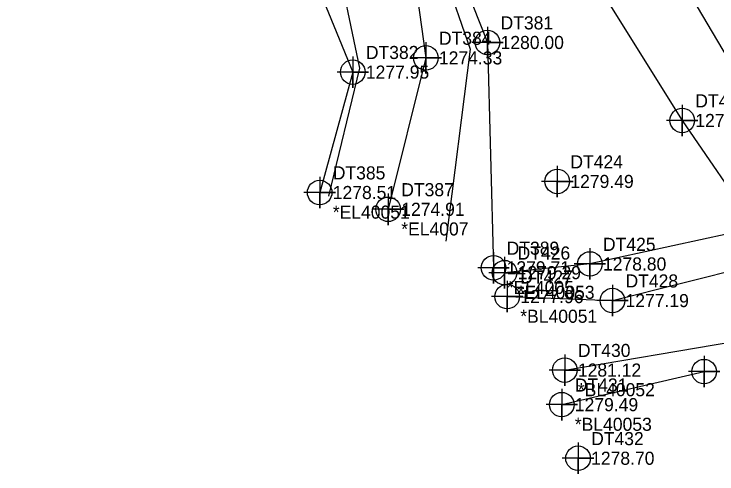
# Model space of a CAD drawing. Extents: x 1394009 to 1394411, y 957864 to 958364.
# Drawn here: x 1394149.6 to 1394283.7, y 957864.1 to 957951.9 of the extents above; entities that cross this region are included whole.
import ezdxf

# ---------------------------------------------------------------- set-up
doc = ezdxf.new("R2010")
doc.units = 0
for name, color, linetype in [('Exist DTM Breakline', 7, 'Continuous'), ('Exist DTM Breakline Cogo Comment', 7, 'Continuous'), ('Exist DTM Breakline Cogo Elevation', 7, 'Continuous'), ('Exist DTM Breakline Cogo Number', 7, 'Continuous'), ('Exist DTM Breakline Cogo Point CELL', 7, 'Continuous'), ('Exist DTM Breakline Underwater', 7, 'Continuous'), ('Exist DTM Breakline Underwater Cogo Comment', 7, 'Continuous'), ('Exist DTM Breakline Underwater Cogo Elevation', 7, 'Continuous'), ('Exist DTM Breakline Underwater Cogo Number', 7, 'Continuous'), ('Exist DTM Breakline Underwater Cogo Point CELL', 7, 'Continuous'), ('Exist DTM Crownline', 7, 'Continuous'), ('Exist DTM Regular Point Cogo Elevation', 7, 'Continuous'), ('Exist Hydro Stream or Body of Water', 7, 'Continuous'), ('Exist Roads EOP', 7, 'Continuous'), ('PH Exist DTM NCFMP LIDAR Elevation Point', 7, 'Continuous'), ('Raster_Level_0', 7, 'Continuous')]:
    doc.layers.add(name, color=color, linetype=linetype)

msp = doc.modelspace()

# ---------------------------------------------------------------- linework, layer by layer
at = {"layer": 'Exist DTM Breakline'}
for p, q in [((1394254.6438, 957883.9212), (1394290.1223, 957889.9518)), ((1394254.0597, 957877.3161), (1394281.2269, 957883.6237))]:
    msp.add_line(p, q, dxfattribs=at)
for points in [[(1394234.7161, 958087.1493), (1394208.4745, 958071.86), (1394207.051, 958069.7897), (1394210.8783, 958071.9618), (1394213.0858, 958066.3393), (1394211.818, 958067.823), (1394208.5647, 958061.9703), (1394223.9737, 958040.8216), (1394237.157, 958012.3346), (1394253.5006, 957985.8224), (1394267.2603, 957974.749), (1394288.6525, 957938.4432), (1394308.2436, 957898.2998)], [(1394205.7466, 958068.8917), (1394190.5711, 958057.2067), (1394189.0222, 958053.5957), (1394184.8806, 958043.8407), (1394186.4655, 958021.4355), (1394191.8774, 958003.2638), (1394213.2872, 957998.1706), (1394228.4733, 957975.4923), (1394239.8888, 957946.4968), (1394241.0497, 957903.4511)], [(1394149.71, 958037.8453), (1394149.558, 958011.2722), (1394170.1298, 957980.5225), (1394177.7403, 957975.0583), (1394196.6522, 957979.7455), (1394205.9408, 957961.0676), (1394214.1868, 957940.8417), (1394207.8738, 957917.8382)], [(1394202.6193, 958029.3354), (1394215.0019, 958016.2345), (1394221.6713, 958003.4334), (1394237.1401, 957997.6779), (1394243.3584, 957984.1351), (1394256.2425, 957964.9576), (1394277.0443, 957931.6004), (1394291.0752, 957911.067), (1394259.429, 957904.1903), (1394243.1444, 957902.5266)], [(1394243.646, 957897.9549), (1394263.7341, 957897.1943), (1394290.0967, 957903.851), (1394301.0447, 957893.1375)]]:
    msp.add_lwpolyline(points, dxfattribs=at)
at = {"layer": 'Exist DTM Breakline Cogo Point CELL'}
for points in [[(1394239.8888, 957949.4968), (1394239.8888, 957943.4968), (1394239.8888, 957946.4968), (1394242.8888, 957946.4968), (1394236.8888, 957946.4968)], [(1394214.1868, 957943.8417), (1394214.1868, 957937.8417), (1394214.1868, 957940.8417), (1394217.1868, 957940.8417), (1394211.1868, 957940.8417)], [(1394277.0443, 957934.6004), (1394277.0443, 957928.6004), (1394277.0443, 957931.6004), (1394280.0443, 957931.6004), (1394274.0443, 957931.6004)], [(1394207.8738, 957920.8382), (1394207.8738, 957914.8382), (1394207.8738, 957917.8382), (1394210.8738, 957917.8382), (1394204.8738, 957917.8382)], [(1394241.0497, 957906.4511), (1394241.0497, 957900.4511), (1394241.0497, 957903.4511), (1394244.0497, 957903.4511), (1394238.0497, 957903.4511)], [(1394259.429, 957907.1903), (1394259.429, 957901.1903), (1394259.429, 957904.1903), (1394262.429, 957904.1903), (1394256.429, 957904.1903)], [(1394243.1444, 957905.5266), (1394243.1444, 957899.5266), (1394243.1444, 957902.5266), (1394246.1444, 957902.5266), (1394240.1444, 957902.5266)], [(1394243.646, 957900.9549), (1394243.646, 957894.9549), (1394243.646, 957897.9549), (1394246.646, 957897.9549), (1394240.646, 957897.9549)], [(1394263.7341, 957900.1943), (1394263.7341, 957894.1943), (1394263.7341, 957897.1943), (1394266.7341, 957897.1943), (1394260.7341, 957897.1943)], [(1394254.6438, 957886.9212), (1394254.6438, 957880.9212), (1394254.6438, 957883.9212), (1394257.6438, 957883.9212), (1394251.6438, 957883.9212)], [(1394281.2269, 957886.6237), (1394281.2269, 957880.6237), (1394281.2269, 957883.6237), (1394284.2269, 957883.6237), (1394278.2269, 957883.6237)], [(1394254.0597, 957880.3161), (1394254.0597, 957874.3161), (1394254.0597, 957877.3161), (1394257.0597, 957877.3161), (1394251.0597, 957877.3161)]]:
    msp.add_lwpolyline(points, dxfattribs=at)
for centre in [(1394239.8888, 957946.4968), (1394214.1868, 957940.8417), (1394277.0443, 957931.6004), (1394207.8738, 957917.8382), (1394259.429, 957904.1903), (1394241.0497, 957903.4511), (1394243.1444, 957902.5266), (1394243.646, 957897.9549), (1394263.7341, 957897.1943), (1394254.6438, 957883.9212), (1394281.2269, 957883.6237), (1394254.0597, 957877.3161)]:
    msp.add_circle(centre, 2.344, dxfattribs=at)
at = {"layer": 'Exist DTM Breakline Underwater'}
msp.add_lwpolyline([(1394192.3583, 958090.5901), (1394178.3868, 958072.1738), (1394169.2021, 958057.4892), (1394167.6851, 958038.5052), (1394159.1429, 958013.4636), (1394180.3464, 957994.6406), (1394199.7643, 957985.953), (1394224.0434, 957972.821), (1394228.1265, 957943.556), (1394220.9394, 957914.628)], dxfattribs=at)
at = {"layer": 'Exist DTM Breakline Underwater Cogo Point CELL'}
for points in [[(1394228.1265, 957946.556), (1394228.1265, 957940.556), (1394228.1265, 957943.556), (1394231.1265, 957943.556), (1394225.1265, 957943.556)], [(1394220.9394, 957917.628), (1394220.9394, 957911.628), (1394220.9394, 957914.628), (1394223.9394, 957914.628), (1394217.9394, 957914.628)]]:
    msp.add_lwpolyline(points, dxfattribs=at)
for centre in [(1394228.1265, 957943.556), (1394220.9394, 957914.628)]:
    msp.add_circle(centre, 2.344, dxfattribs=at)
at = {"layer": 'Exist DTM Crownline'}
msp.add_spline([(1394223.6604, 958072.3799), (1394244.8218, 958037.3795), (1394269.4506, 957997.0996), (1394294.4399, 957957.1952), (1394318.0033, 957919.003)], degree=3, dxfattribs=at)
at = {"layer": 'Exist Hydro Stream or Body of Water'}
for points in [[(1394190.7058, 958095.3239), (1394177.2279, 958076.1665), (1394160.3309, 958063.4331), (1394156.4808, 958036.0172), (1394151.8807, 958011.6814), (1394172.2345, 957982.059), (1394181.0188, 957978.4843), (1394196.9657, 957983.1686), (1394210.7106, 957964.4319), (1394215.4703, 957941.598), (1394209.5541, 957917.1532)], [(1394203.9517, 958072.4517), (1394187.582, 958060.0115), (1394178.1893, 958051.3287), (1394177.8231, 958039.3974), (1394183.6296, 958020.3053), (1394189.4903, 958000.9486), (1394211.9273, 957995.783), (1394226.7784, 957973.5412), (1394236.5763, 957945.2073), (1394231.9355, 957908.562)]]:
    msp.add_lwpolyline(points, dxfattribs=at)
at = {"layer": 'Exist Roads EOP'}
for points in [[(1394231.4675, 958077.1435), (1394252.9816, 958042.2643), (1394277.1668, 958002.5538), (1394302.3527, 957962.1709), (1394325.7525, 957924.4929)], [(1394215.8384, 958067.9044), (1394237.3577, 958032.1628), (1394261.7049, 957991.7458), (1394286.4849, 957951.9331), (1394310.1777, 957914.0367)]]:
    msp.add_spline(points, degree=3, dxfattribs=at)
at = {"layer": 'PH Exist DTM NCFMP LIDAR Elevation Point'}
for points in [[(1394253.2102, 957922.9532), (1394253.2102, 957916.9532), (1394253.2102, 957919.9532), (1394256.2102, 957919.9532), (1394250.2102, 957919.9532)], [(1394257.1683, 957870.0757), (1394257.1683, 957864.0757), (1394257.1683, 957867.0757), (1394260.1683, 957867.0757), (1394254.1683, 957867.0757)]]:
    msp.add_lwpolyline(points, dxfattribs=at)
for centre in [(1394253.2102, 957919.9532), (1394257.1683, 957867.0757)]:
    msp.add_circle(centre, 2.344, dxfattribs=at)

# ---------------------------------------------------------------- texts
at = {"layer": 'Exist DTM Breakline Cogo Comment'}
for s, p in [('*EL40051', (1394210.3738, 957912.8382)), ('*EL4005', (1394243.5497, 957898.4511)), ('*EL40053', (1394245.6444, 957897.5266)), ('*BL40051', (1394246.146, 957892.9549)), ('*BL40052', (1394257.1438, 957878.9212)), ('*BL40053', (1394256.5597, 957872.3161))]:
    msp.add_text(s, height=2.5, dxfattribs=at).set_placement(p)
at = {"layer": 'Exist DTM Breakline Cogo Elevation'}
for s, p in [('1280.00', (1394242.3888, 957945.2468)), ('1277.95', (1394216.6868, 957939.5917)), ('1279.75', (1394279.5443, 957930.3504)), ('1278.51', (1394210.3738, 957916.5882)), ('1279.71', (1394243.5497, 957902.2011)), ('1278.80', (1394261.929, 957902.9403)), ('1279.29', (1394245.6444, 957901.2766)), ('1277.96', (1394246.146, 957896.7049)), ('1277.19', (1394266.2341, 957895.9443)), ('1281.12', (1394257.1438, 957882.6712)), ('1279.49', (1394256.5597, 957876.0661))]:
    msp.add_text(s, height=2.5, dxfattribs=at).set_placement(p)
at = {"layer": 'Exist DTM Breakline Cogo Number'}
for s, p in [('DT381', (1394242.3888, 957948.9968)), ('DT382', (1394216.6868, 957943.3417)), ('DT422', (1394279.5443, 957934.1004)), ('DT385', (1394210.3738, 957920.3382)), ('DT425', (1394261.929, 957906.6903)), ('DT389', (1394243.5497, 957905.9511)), ('DT426', (1394245.6444, 957905.0266)), ('DT427', (1394246.146, 957900.4549)), ('DT428', (1394266.2341, 957899.6943)), ('DT430', (1394257.1438, 957886.4212)), ('DT431', (1394256.5597, 957879.8161))]:
    msp.add_text(s, height=2.5, dxfattribs=at).set_placement(p)
at = {"layer": 'Exist DTM Breakline Underwater Cogo Comment'}
msp.add_text('*EL4007', height=2.5, dxfattribs=at).set_placement((1394223.4394, 957909.628))
at = {"layer": 'Exist DTM Breakline Underwater Cogo Elevation'}
for s, p in [('1274.33', (1394230.6265, 957942.306)), ('1274.91', (1394223.4394, 957913.378))]:
    msp.add_text(s, height=2.5, dxfattribs=at).set_placement(p)
at = {"layer": 'Exist DTM Breakline Underwater Cogo Number'}
for s, p in [('DT384', (1394230.6265, 957946.056)), ('DT387', (1394223.4394, 957917.128))]:
    msp.add_text(s, height=2.5, dxfattribs=at).set_placement(p)
at = {"layer": 'Exist DTM Regular Point Cogo Elevation'}
for s, p in [('1279.49', (1394255.7102, 957918.7032)), ('1278.70', (1394259.6683, 957865.8257))]:
    msp.add_text(s, height=2.5, dxfattribs=at).set_placement(p)
at = {"layer": 'Raster_Level_0'}
for s, p in [('DT424', (1394255.7102, 957922.4532)), ('DT432', (1394259.6683, 957869.5757))]:
    msp.add_text(s, height=2.5, dxfattribs=at).set_placement(p)

doc.saveas('drawing.dxf')
